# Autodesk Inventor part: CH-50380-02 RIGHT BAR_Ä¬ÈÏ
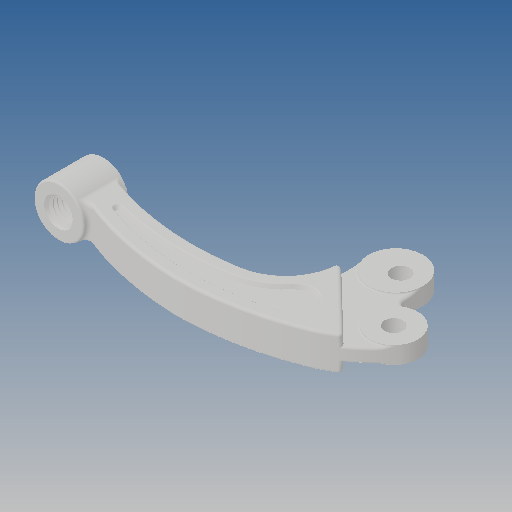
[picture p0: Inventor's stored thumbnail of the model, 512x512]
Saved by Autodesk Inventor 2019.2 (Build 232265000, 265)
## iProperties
Created: 2010-06
Part Number: CH-50380-02 RIGHT BAR_Ä¬ÈÏ
Material: Ogólny
Document SubType Name: Modeling
Designer: CADENGINEERING4
Density: 1 g/cm^3
Appearance: Domyślna
Author: CADENGINEERING4
Revision Number: ÈÎºÎ
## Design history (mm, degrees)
feature "NONE"
node "Bryła1"
